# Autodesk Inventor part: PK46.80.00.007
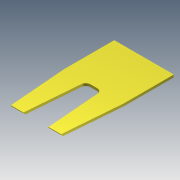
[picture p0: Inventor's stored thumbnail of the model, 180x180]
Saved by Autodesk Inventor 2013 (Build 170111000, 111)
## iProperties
Shininess: 64.0
Length Units: 11269
Angle Units: 11279
Time Units: 11290
Mass Units: 11283
Length Display Precision: 3
Angle Display Precision: 2
Compacted: True
Part Number: PK46.80.00.007
Document SubType Name: Modeling
Created: 2005-01
Material: Steel, Mild
Designer: SAlex
Manufacturer: Standard
Standards Organization: Custom
Density: 7.86 g/cm^3
Mass: 25478.1 g
Surface Area: 4491.32 cm^2
Volume: 3241.49 cm^3
Density: 0.0
Volumn: 0.0
Area: 0.0
PropertySet Name: Model Information
Control State: 0
Master: False
Checked Out: False
Checked Out Date: 2008-10-15
Last Check In Date: 2008-10-15
Author: SAlex
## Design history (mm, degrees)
sketch "Sketch1"
  geometry: L1 (0, 0)-(0, -320); L2 (0, -320)-(30, -690); L3 (30, -690)-(110, -690); L4 (110, -690)-(140, -320); L5 (140, -320)-(240, -320); L6 (240, -320)-(270, -690); L7 (270, -690)-(350, -690); L8 (350, -690)-(380, -320); L9 (380, -320)-(380, 0); L10 (380, 0)-(0, 0)
  constraints: 20 end point, 3 parallel, 2 collinear, 2 equal length, 1 perpendicular, 1 vertical, 1 other
  dimensions: "d0" = 380 distance of L9.end L1.start; "d1" = 690 distance between parallel lines of L10 L7; "d2" = 320 distance between parallel lines of L5 L10; "d3" = 320 distance of L8.end L9.end; "d4" = 80 distance of L6.end L7.end; "d5" = 80 distance of L2.end L3.end; "d6" = 100 distance of L4.end L5.end; "d7" = 140 distance from line of L5.end L9; "d8" = 30 distance from line of L7.end L9
extrude "Extrusion1" new body sketch "Sketch1" distance "d9" = 16; taper "d10" = 0 deg
fillet "Fillet1" dims "d11" = 30
chamfer "Chamfer1" distance "d12" = 12; stored, may be unused: second distance "d13" = 2, angle "d14" = 45 deg
body "Solid1"
